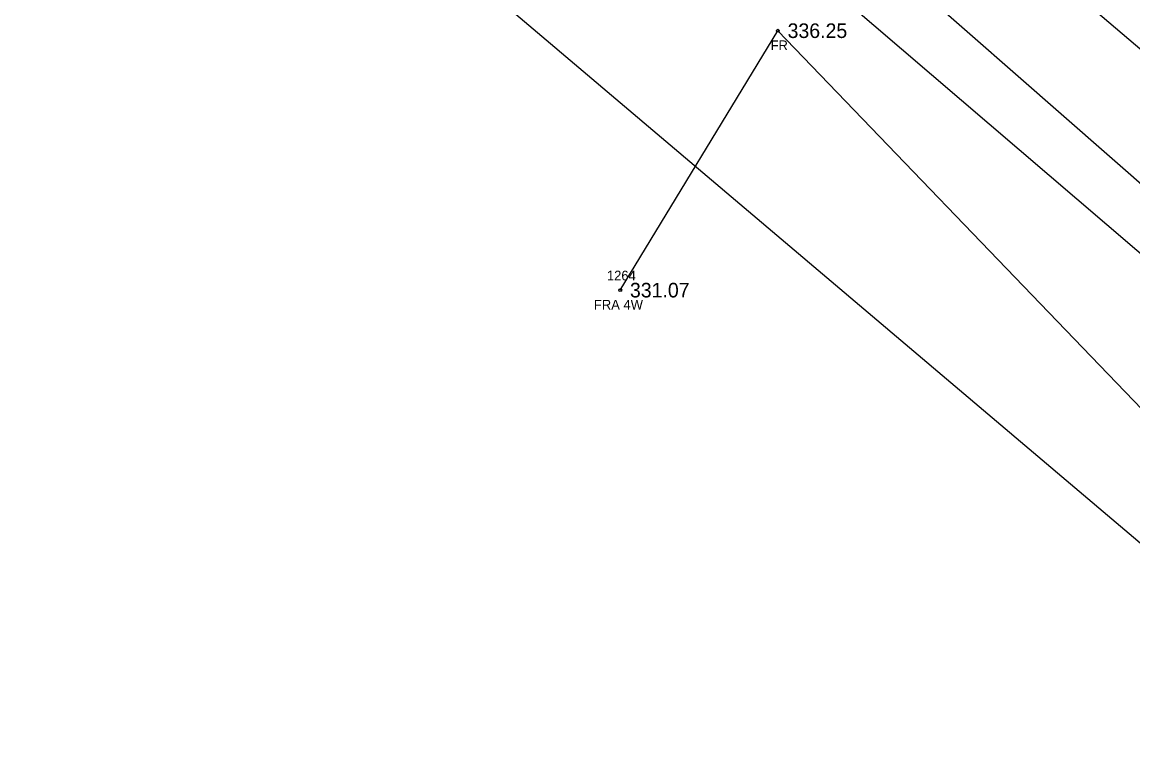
# Model space of a CAD drawing. Extents: x 2006517 to 2008868, y 1001613 to 1004633.
# Drawn here: x 2007831.6 to 2007945.8, y 1002790.5 to 1002865.2 of the extents above; entities that cross this region are included whole.
import ezdxf

# ---------------------------------------------------------------- set-up
doc = ezdxf.new("R2010")
doc.units = 0
for name, color, linetype in [('RD_EX_Fence_Other', 7, 'Continuous'), ('RD_EX_Fence_Other_txCode', 7, 'Continuous'), ('RD_EX_GuardRail', 7, 'Continuous'), ('RD_EX_Road', 7, 'Continuous'), ('RD_EX_TX_Fence_Other_ELEV', 7, 'Continuous'), ('RD_EX_VEG', 7, 'Continuous'), ('RD_HC_Cl', 7, 'Continuous'), ('RD_SMD_Locator', 7, 'Continuous')]:
    doc.layers.add(name, color=color, linetype=linetype)

msp = doc.modelspace()

# ---------------------------------------------------------------- linework, layer by layer
at = {"layer": 'RD_EX_Fence_Other'}
msp.add_lwpolyline([(2007893.11, 1002837.65), (2007909.33, 1002864.32), (2007977.3, 1002793.73), (2008015.3, 1002762.96), (2008043.08, 1002729.4), (2008077.68, 1002692.52), (2008105.37, 1002656.99), (2008134.4, 1002618.61), (2008158.01, 1002583.52)], dxfattribs=at)
at = {"layer": 'RD_EX_GuardRail'}
msp.add_lwpolyline([(2007623.33, 1003114.9), (2007686.46, 1003063.73), (2007759.92, 1003000.81), (2007833.42, 1002938.17), (2007916.12, 1002867.57), (2007997.28, 1002798.14)], dxfattribs=at)
at = {"layer": 'RD_EX_Road'}
msp.add_lwpolyline([(2007926.53, 1002880.46), (2007919.41, 1002872.5), (2007991.54, 1002809.35), (2008026.83, 1002776.85), (2008062.37, 1002741.51), (2008093.99, 1002707.06), (2008125.02, 1002669.01), (2008154.41, 1002630.27), (2008179.59, 1002592.85), (2008187.94, 1002580.41), (2008232, 1002511.78), (2008283.05, 1002433.59)], dxfattribs=at)
at = {"layer": 'RD_EX_VEG'}
msp.add_lwpolyline([(2007395.89, 1003327.12), (2007429.8, 1003285.17), (2007467.04, 1003247.92), (2007498.61, 1003210.85), (2007670.4, 1003045.37), (2007967.56, 1002793.96), (2008054.61, 1002736.66), (2008078.76, 1002693.39), (2008113.28, 1002661.09), (2008135.36, 1002619.06), (2008159.5, 1002583.06), (2008222.5, 1002503.36), (2008272.84, 1002426.91), (2008323.43, 1002347.7), (2008431.42, 1002192), (2008479.95, 1002108.23), (2008533.09, 1002033.28), (2008631.97, 1001873.89), (2008775.08, 1001653.06)], dxfattribs=at)
at = {"layer": 'RD_HC_Cl'}
msp.add_line((2007559.77, 1003192.01), (2007994.36, 1002821.78), dxfattribs=at)
at = {"layer": 'RD_SMD_Locator'}
for centre in [(2007909.33, 1002864.32), (2007893.11, 1002837.65)]:
    msp.add_circle(centre, 0.15, dxfattribs=at)

# ---------------------------------------------------------------- texts
at = {"layer": 'RD_EX_Fence_Other_txCode'}
for s, p in [('FR', (2007908.58, 1002862.32)), ('1264', (2007891.74, 1002838.65)), ('FRA 4W', (2007890.4, 1002835.65))]:
    msp.add_text(s, height=1, dxfattribs=at).set_placement(p)
at = {"layer": 'RD_EX_TX_Fence_Other_ELEV'}
for s, p in [('336.25', (2007910.33, 1002863.57)), ('331.07', (2007894.11, 1002836.9))]:
    msp.add_text(s, height=1.5, dxfattribs=at).set_placement(p)

doc.saveas('drawing.dxf')
